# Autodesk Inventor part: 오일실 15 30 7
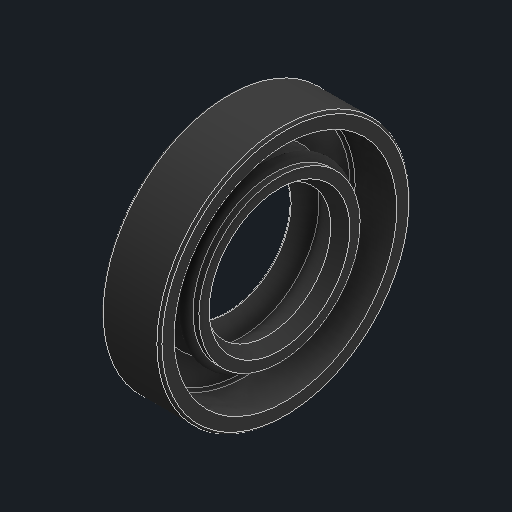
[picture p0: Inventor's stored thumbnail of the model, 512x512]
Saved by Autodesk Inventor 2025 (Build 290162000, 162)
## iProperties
Created: 2025-08
Part Number: 오일실 15 30 7
Material: 고무
Description: 오일-실
Document SubType Name: Modeling
Designer: infra15
Density: 0.93 g/cm^3
Appearance: 기본값
Author: jhkim
Sending System: Autodesk Inventor 2026
Preprocessor: ST-DEVELOPER v20.1
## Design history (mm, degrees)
feature "Solid1"
node "솔리드1"
